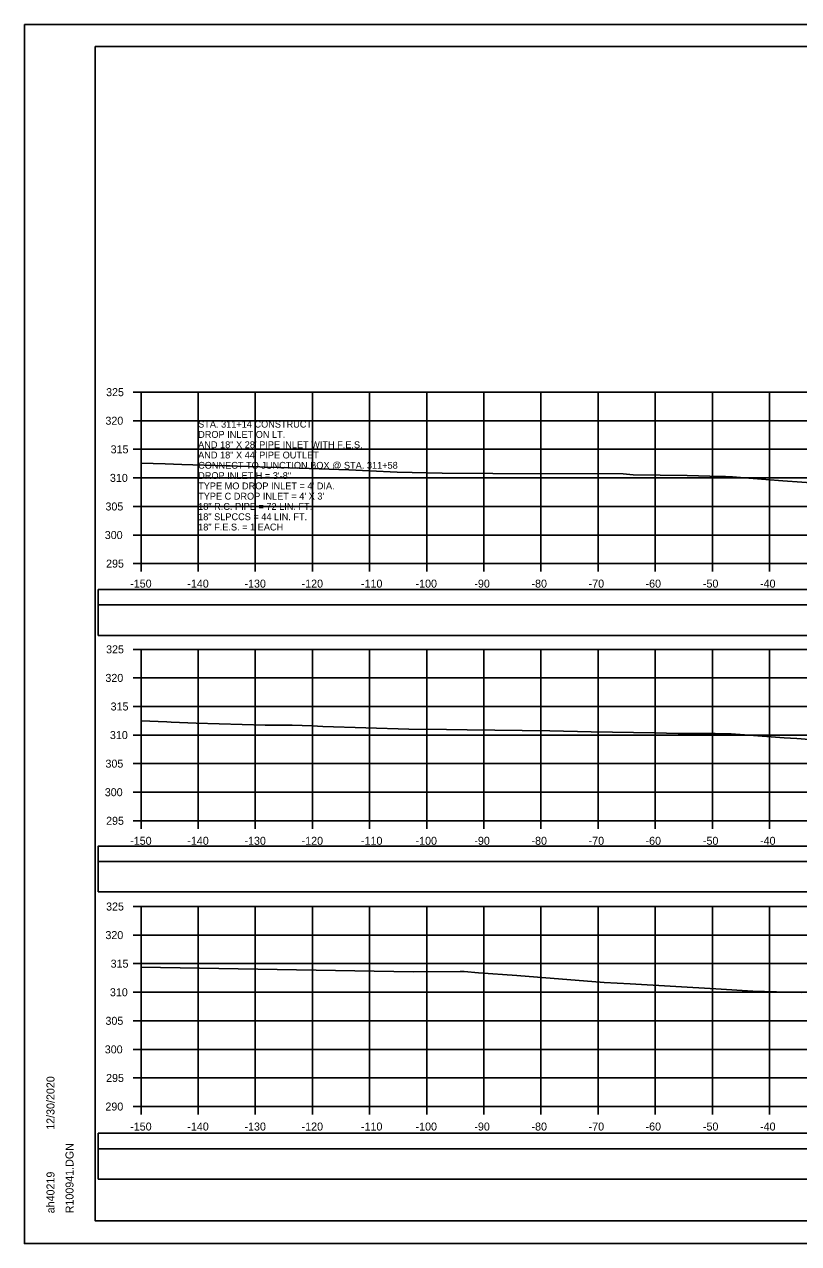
# Model space of a CAD drawing. Extents: x 1370538 to 1372872, y 376220 to 381127.
# Drawn here: x 1370538.2 to 1370673.7, y 378064.2 to 378277.5 of the extents above; entities that cross this region are included whole.
import ezdxf

# ---------------------------------------------------------------- set-up
doc = ezdxf.new("R2010")
doc.units = 0
for name, color, linetype in [('R_Border Notes', 7, 'Continuous'), ('R_Border PE', 7, 'Continuous'), ('R_Border Prem', 7, 'Continuous'), ('R_Dimension', 7, 'Continuous'), ('R_Grid', 7, 'Continuous'), ('R_Horz Alg Annot', 7, 'Continuous'), ('R_No Plot', 7, 'Continuous'), ('R_Water Annot', 7, 'Continuous')]:
    doc.layers.add(name, color=color, linetype=linetype)

msp = doc.modelspace()

# ---------------------------------------------------------------- linework, layer by layer
at = {"layer": 'R_Border Notes'}
for p, q in [((1370550.61, 378273.65), (1370866.79, 378273.65)), ((1370550.61, 378068.19), (1370550.61, 378273.65)), ((1370550.61, 378068.19), (1370550.61, 378068.19)), ((1370866.79, 378068.19), (1370550.61, 378068.19))]:
    msp.add_line(p, q, dxfattribs=at)
at = {"layer": 'R_Border Prem'}
for p, q in [((1370557.21, 378213.19), (1370558.61, 378213.19)), ((1370558.61, 378183.19), (1370558.61, 378213.19)), ((1370557.21, 378208.19), (1370558.61, 378208.19)), ((1370557.21, 378203.19), (1370558.61, 378203.19)), ((1370557.21, 378198.19), (1370558.61, 378198.19)), ((1370557.21, 378193.19), (1370558.61, 378193.19)), ((1370557.21, 378188.19), (1370558.61, 378188.19)), ((1370557.21, 378183.19), (1370558.61, 378183.19)), ((1370558.61, 378183.19), (1370858.61, 378183.19)), ((1370558.61, 378181.79), (1370558.61, 378183.19)), ((1370568.61, 378181.79), (1370568.61, 378183.19)), ((1370578.61, 378181.79), (1370578.61, 378183.19)), ((1370588.61, 378181.79), (1370588.61, 378183.19)), ((1370598.61, 378181.79), (1370598.61, 378183.19)), ((1370608.61, 378181.79), (1370608.61, 378183.19)), ((1370618.61, 378181.79), (1370618.61, 378183.19)), ((1370628.61, 378181.79), (1370628.61, 378183.19)), ((1370638.61, 378181.79), (1370638.61, 378183.19)), ((1370648.61, 378181.79), (1370648.61, 378183.19)), ((1370658.61, 378181.79), (1370658.61, 378183.19)), ((1370668.61, 378181.79), (1370668.61, 378183.19)), ((1370557.21, 378168.19), (1370558.61, 378168.19)), ((1370558.61, 378138.19), (1370558.61, 378168.19)), ((1370557.21, 378163.19), (1370558.61, 378163.19)), ((1370557.21, 378158.19), (1370558.61, 378158.19)), ((1370557.21, 378153.19), (1370558.61, 378153.19)), ((1370557.21, 378148.19), (1370558.61, 378148.19)), ((1370557.21, 378143.19), (1370558.61, 378143.19)), ((1370557.21, 378138.19), (1370558.61, 378138.19)), ((1370558.61, 378138.19), (1370858.61, 378138.19)), ((1370558.61, 378136.79), (1370558.61, 378138.19)), ((1370568.61, 378136.79), (1370568.61, 378138.19)), ((1370578.61, 378136.79), (1370578.61, 378138.19)), ((1370588.61, 378136.79), (1370588.61, 378138.19)), ((1370598.61, 378136.79), (1370598.61, 378138.19)), ((1370608.61, 378136.79), (1370608.61, 378138.19)), ((1370618.61, 378136.79), (1370618.61, 378138.19)), ((1370628.61, 378136.79), (1370628.61, 378138.19)), ((1370638.61, 378136.79), (1370638.61, 378138.19)), ((1370648.61, 378136.79), (1370648.61, 378138.19)), ((1370658.61, 378136.79), (1370658.61, 378138.19)), ((1370668.61, 378136.79), (1370668.61, 378138.19)), ((1370557.21, 378123.19), (1370558.61, 378123.19)), ((1370558.61, 378088.19), (1370558.61, 378123.19)), ((1370557.21, 378118.19), (1370558.61, 378118.19)), ((1370557.21, 378113.19), (1370558.61, 378113.19)), ((1370557.21, 378108.19), (1370558.61, 378108.19)), ((1370557.21, 378103.19), (1370558.61, 378103.19)), ((1370557.21, 378098.19), (1370558.61, 378098.19)), ((1370557.21, 378093.19), (1370558.61, 378093.19)), ((1370557.21, 378088.19), (1370558.61, 378088.19)), ((1370558.61, 378088.19), (1370858.61, 378088.19)), ((1370558.61, 378086.79), (1370558.61, 378088.19)), ((1370568.61, 378086.79), (1370568.61, 378088.19)), ((1370578.61, 378086.79), (1370578.61, 378088.19)), ((1370588.61, 378086.79), (1370588.61, 378088.19)), ((1370598.61, 378086.79), (1370598.61, 378088.19)), ((1370608.61, 378086.79), (1370608.61, 378088.19)), ((1370618.61, 378086.79), (1370618.61, 378088.19)), ((1370628.61, 378086.79), (1370628.61, 378088.19)), ((1370638.61, 378086.79), (1370638.61, 378088.19)), ((1370648.61, 378086.79), (1370648.61, 378088.19)), ((1370658.61, 378086.79), (1370658.61, 378088.19)), ((1370668.61, 378086.79), (1370668.61, 378088.19))]:
    msp.add_line(p, q, dxfattribs=at)
at = {"layer": 'R_Dimension'}
for points in [[(1370558.61, 378200.79), (1370562.82, 378200.65), (1370565.76, 378200.55), (1370579.39, 378200.1), (1370580.35, 378200.07), (1370582.83, 378199.98), (1370594.97, 378199.58), (1370598.59, 378199.4), (1370603.44, 378199.18), (1370611.34, 378199.03), (1370620.16, 378198.94), (1370642.98, 378198.87), (1370644.76, 378198.73), (1370654.19, 378198.63), (1370658.16, 378198.5), (1370660.89, 378198.42), (1370662.11, 378198.37), (1370665.01, 378198.14), (1370670.91, 378197.7), (1370677.56, 378197.18)], [(1370558.61, 378155.66), (1370563.13, 378155.49), (1370563.86, 378155.47), (1370568.28, 378155.3), (1370580.33, 378154.9), (1370585.05, 378154.92), (1370588.57, 378154.8), (1370590.44, 378154.71), (1370605.49, 378154.25), (1370612.06, 378154.18), (1370615.71, 378154.1), (1370630.17, 378153.91), (1370637.42, 378153.75), (1370648.55, 378153.58), (1370652.62, 378153.48), (1370657.92, 378153.49), (1370659.11, 378153.47), (1370661.87, 378153.39), (1370668.91, 378152.88), (1370671.15, 378152.73), (1370673.36, 378152.58), (1370680.76, 378152.03)], [(1370558.61, 378112.55), (1370606.26, 378111.75), (1370614.46, 378111.81), (1370615.14, 378111.8), (1370617.68, 378111.58), (1370624.39, 378111.09), (1370639.68, 378109.92), (1370644.19, 378109.66), (1370659.2, 378108.79), (1370665.71, 378108.39), (1370669.83, 378108.27), (1370672.94, 378108.18), (1370674.16, 378108.14)]]:
    msp.add_lwpolyline(points, dxfattribs=at)
at = {"layer": 'R_Grid'}
for p, q in [((1370558.61, 378213.19), (1370858.61, 378213.19)), ((1370558.61, 378183.19), (1370558.61, 378213.19)), ((1370568.61, 378183.19), (1370568.61, 378213.19)), ((1370578.61, 378183.19), (1370578.61, 378213.19)), ((1370588.61, 378183.19), (1370588.61, 378213.19)), ((1370598.61, 378183.19), (1370598.61, 378213.19)), ((1370608.61, 378183.19), (1370608.61, 378213.19)), ((1370618.61, 378183.19), (1370618.61, 378213.19)), ((1370628.61, 378183.19), (1370628.61, 378213.19)), ((1370638.61, 378183.19), (1370638.61, 378213.19)), ((1370648.61, 378183.19), (1370648.61, 378213.19)), ((1370658.61, 378183.19), (1370658.61, 378213.19)), ((1370668.61, 378183.19), (1370668.61, 378213.19)), ((1370558.61, 378208.19), (1370858.61, 378208.19)), ((1370558.61, 378203.19), (1370858.61, 378203.19)), ((1370558.61, 378198.19), (1370858.61, 378198.19)), ((1370558.61, 378193.19), (1370858.61, 378193.19)), ((1370558.61, 378188.19), (1370858.61, 378188.19)), ((1370558.61, 378183.19), (1370858.61, 378183.19)), ((1370558.61, 378168.19), (1370858.61, 378168.19)), ((1370558.61, 378138.19), (1370558.61, 378168.19)), ((1370568.61, 378138.19), (1370568.61, 378168.19)), ((1370578.61, 378138.19), (1370578.61, 378168.19)), ((1370588.61, 378138.19), (1370588.61, 378168.19)), ((1370598.61, 378138.19), (1370598.61, 378168.19)), ((1370608.61, 378138.19), (1370608.61, 378168.19)), ((1370618.61, 378138.19), (1370618.61, 378168.19)), ((1370628.61, 378138.19), (1370628.61, 378168.19)), ((1370638.61, 378138.19), (1370638.61, 378168.19)), ((1370648.61, 378138.19), (1370648.61, 378168.19)), ((1370658.61, 378138.19), (1370658.61, 378168.19)), ((1370668.61, 378138.19), (1370668.61, 378168.19)), ((1370558.61, 378163.19), (1370858.61, 378163.19)), ((1370558.61, 378158.19), (1370858.61, 378158.19)), ((1370558.61, 378153.19), (1370858.61, 378153.19)), ((1370558.61, 378148.19), (1370858.61, 378148.19)), ((1370558.61, 378143.19), (1370858.61, 378143.19)), ((1370558.61, 378138.19), (1370858.61, 378138.19)), ((1370558.61, 378123.19), (1370858.61, 378123.19)), ((1370558.61, 378088.19), (1370558.61, 378123.19)), ((1370568.61, 378088.19), (1370568.61, 378123.19)), ((1370578.61, 378088.19), (1370578.61, 378123.19)), ((1370588.61, 378088.19), (1370588.61, 378123.19)), ((1370598.61, 378088.19), (1370598.61, 378123.19)), ((1370608.61, 378088.19), (1370608.61, 378123.19)), ((1370618.61, 378088.19), (1370618.61, 378123.19)), ((1370628.61, 378088.19), (1370628.61, 378123.19)), ((1370638.61, 378088.19), (1370638.61, 378123.19)), ((1370648.61, 378088.19), (1370648.61, 378123.19)), ((1370658.61, 378088.19), (1370658.61, 378123.19)), ((1370668.61, 378088.19), (1370668.61, 378123.19)), ((1370558.61, 378118.19), (1370858.61, 378118.19)), ((1370558.61, 378113.19), (1370858.61, 378113.19)), ((1370558.61, 378108.19), (1370858.61, 378108.19)), ((1370558.61, 378103.19), (1370858.61, 378103.19)), ((1370558.61, 378098.19), (1370858.61, 378098.19)), ((1370558.61, 378093.19), (1370858.61, 378093.19)), ((1370558.61, 378088.19), (1370858.61, 378088.19))]:
    msp.add_line(p, q, dxfattribs=at)
at = {"layer": 'R_Horz Alg Annot'}
for points in [[(1370551.13, 378175.95), (1370866.25, 378175.95), (1370866.25, 378178.66), (1370551.13, 378178.66)], [(1370551.13, 378170.63), (1370866.25, 378170.63), (1370866.25, 378175.95), (1370551.13, 378175.95)], [(1370551.13, 378131.06), (1370866.25, 378131.06), (1370866.25, 378133.77), (1370551.13, 378133.77)], [(1370551.13, 378125.74), (1370866.25, 378125.74), (1370866.25, 378131.06), (1370551.13, 378131.06)], [(1370551.13, 378080.81), (1370866.25, 378080.81), (1370866.25, 378083.52), (1370551.13, 378083.52)], [(1370551.13, 378075.49), (1370866.25, 378075.49), (1370866.25, 378080.81), (1370551.13, 378080.81)]]:
    msp.add_lwpolyline(points, close=True, dxfattribs=at)
at = {"layer": 'R_No Plot'}
for p, q in [((1370538.21, 378277.54), (1370871.54, 378277.54)), ((1370538.21, 378064.21), (1370871.54, 378064.21))]:
    msp.add_line(p, q, dxfattribs=at)
for points in [[(1370538.2, 378277.54), (1370871.54, 378277.54), (1370871.54, 378064.2), (1370538.2, 378064.2)], [(1370784.53, 378273.65), (1370784.53, 378263.77), (1370820.26, 378263.77), (1370820.26, 378260.85), (1370843.46, 378260.85), (1370843.46, 378236.52), (1370866.79, 378236.52), (1370866.79, 378068.19), (1370550.61, 378068.19), (1370550.61, 378273.65)]]:
    msp.add_lwpolyline(points, close=True, dxfattribs=at)

# ---------------------------------------------------------------- texts
at = {"layer": 'R_Border Notes'}
for s, p in [('12/30/2020', (1370543.47, 378084.12)), ('R100941.DGN', (1370546.8, 378069.51)), ('ah40219', (1370543.47, 378069.51))]:
    msp.add_text(s, height=1.4, rotation=90, dxfattribs=at).set_placement(p)
at = {"layer": 'R_Border PE'}
for s, p in [('325', (1370552.5, 378212.49)), ('320', (1370552.38, 378207.49)), ('315', (1370553.29, 378202.49)), ('310', (1370553.17, 378197.49)), ('305', (1370552.39, 378192.49)), ('300', (1370552.27, 378187.49)), ('295', (1370552.5, 378182.49)), ('-150', (1370556.72, 378178.99)), ('-140', (1370566.72, 378178.99)), ('-130', (1370576.72, 378178.99)), ('-120', (1370586.72, 378178.99)), ('-110', (1370597.11, 378178.99)), ('-100', (1370606.66, 378178.99)), ('-90', (1370616.95, 378178.99)), ('-80', (1370626.95, 378178.99)), ('-70', (1370636.95, 378178.99)), ('-60', (1370646.91, 378178.99)), ('-50', (1370656.95, 378178.99)), ('-40', (1370666.95, 378178.99)), ('325', (1370552.5, 378167.49)), ('320', (1370552.38, 378162.49)), ('315', (1370553.29, 378157.49)), ('310', (1370553.17, 378152.49)), ('305', (1370552.39, 378147.49)), ('300', (1370552.27, 378142.49)), ('295', (1370552.5, 378137.49)), ('-150', (1370556.72, 378133.99)), ('-140', (1370566.72, 378133.99)), ('-130', (1370576.72, 378133.99)), ('-120', (1370586.72, 378133.99)), ('-110', (1370597.11, 378133.99)), ('-100', (1370606.66, 378133.99)), ('-90', (1370616.95, 378133.99)), ('-80', (1370626.95, 378133.99)), ('-70', (1370636.95, 378133.99)), ('-60', (1370646.91, 378133.99)), ('-50', (1370656.95, 378133.99)), ('-40', (1370666.95, 378133.99)), ('325', (1370552.5, 378122.49)), ('320', (1370552.38, 378117.49)), ('315', (1370553.29, 378112.49)), ('310', (1370553.17, 378107.49)), ('305', (1370552.39, 378102.49)), ('300', (1370552.27, 378097.49)), ('295', (1370552.5, 378092.49)), ('290', (1370552.38, 378087.49)), ('-150', (1370556.72, 378083.99)), ('-140', (1370566.72, 378083.99)), ('-130', (1370576.72, 378083.99)), ('-120', (1370586.72, 378083.99)), ('-110', (1370597.11, 378083.99)), ('-100', (1370606.66, 378083.99)), ('-90', (1370616.95, 378083.99)), ('-80', (1370626.95, 378083.99)), ('-70', (1370636.95, 378083.99)), ('-60', (1370646.91, 378083.99)), ('-50', (1370656.95, 378083.99)), ('-40', (1370666.95, 378083.99))]:
    msp.add_text(s, height=1.4, dxfattribs=at).set_placement(p)
at = {"layer": 'R_Water Annot'}
for s, p in [('STA. 311+14 CONSTRUCT', (1370568.61, 378206.99)), ('DROP INLET ON LT.', (1370568.61, 378205.19)), ('AND 18" X 28\' PIPE INLET WITH F.E.S.', (1370568.61, 378203.39)), ('AND 18" X 44\' PIPE OUTLET', (1370568.61, 378201.59)), ('CONNECT TO JUNCTION BOX @ STA. 311+58', (1370568.61, 378199.79)), ('DROP INLET H = 3\'-8"', (1370568.61, 378197.99)), ("TYPE MO DROP INLET = 4' DIA.", (1370568.61, 378196.19)), ("TYPE C DROP INLET = 4' X 3'", (1370568.61, 378194.39)), ('18" R.C. PIPE = 72 LIN. FT.', (1370568.61, 378192.59)), ('18" SLPCCS = 44 LIN. FT.', (1370568.61, 378190.79)), ('18" F.E.S. = 1 EACH', (1370568.61, 378188.99))]:
    msp.add_text(s, height=1.2, dxfattribs=at).set_placement(p)

doc.saveas('drawing.dxf')
